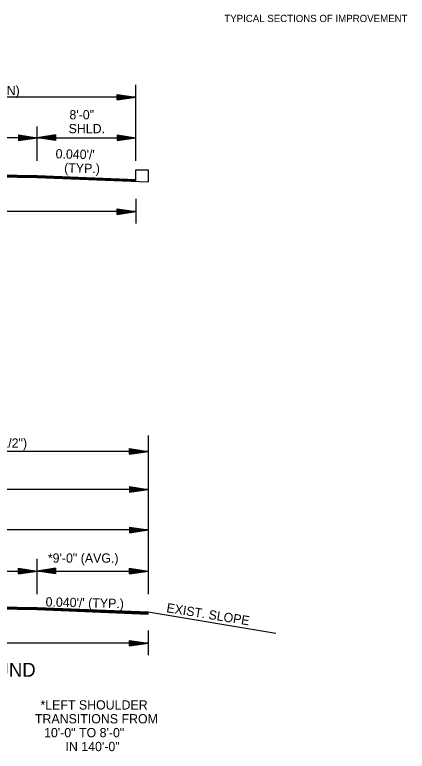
# Model space of a CAD drawing. Extents: x 542112 to 1930787, y -1968972 to 596640.
# Drawn here: x 545437 to 545755, y -1958354 to -1957756 of the extents above; entities that cross this region are included whole.
import ezdxf

# ---------------------------------------------------------------- set-up
doc = ezdxf.new("R2010")
doc.units = 0
for name, color, linetype in [('R_Border', 7, 'Continuous'), ('R_Border Prem', 7, 'Continuous'), ('R_Draft', 7, 'Continuous')]:
    doc.layers.add(name, color=color, linetype=linetype)

msp = doc.modelspace()

# ---------------------------------------------------------------- linework, layer by layer
at = {"layer": 'R_Border'}
for p, q in [((545534.98, -1957891.55), (545534.98, -1957882.14)), ((545534.98, -1957882.14), (545545.15, -1957882.14)), ((545545.15, -1957882.14), (545545.15, -1957891.96))]:
    msp.add_line(p, q, dxfattribs=at)
at = {"layer": 'R_Draft'}
for p, q in [((545534.98, -1957874.9), (545534.98, -1957813.41)), ((545534.98, -1957823.3), (545134.98, -1957823.3)), ((545504.98, -1957823.3), (545224.98, -1957823.3)), ((545519.98, -1957821.05), (545534.98, -1957823.3)), ((545519.98, -1957825.55), (545519.98, -1957821.05)), ((545519.98, -1957821.43), (545532.48, -1957823.3)), ((545519.98, -1957821.81), (545529.9, -1957823.3)), ((545519.98, -1957822.19), (545527.4, -1957823.3)), ((545519.98, -1957822.57), (545524.86, -1957823.3)), ((545519.98, -1957822.95), (545522.35, -1957823.3)), ((545519.98, -1957825.55), (545534.98, -1957823.3)), ((545519.98, -1957824.03), (545524.86, -1957823.3)), ((545519.98, -1957824.8), (545529.9, -1957823.3)), ((545519.98, -1957825.18), (545532.48, -1957823.3)), ((545519.98, -1957824.42), (545527.4, -1957823.3)), ((545519.98, -1957823.66), (545522.35, -1957823.3)), ((545454.98, -1957874.9), (545454.98, -1957846.95)), ((545454.98, -1957856.14), (545334.98, -1957856.14)), ((545439.98, -1957853.89), (545454.98, -1957856.14)), ((545439.98, -1957853.89), (545439.98, -1957858.39)), ((545439.98, -1957854.26), (545452.48, -1957856.14)), ((545439.98, -1957854.65), (545449.9, -1957856.14)), ((545439.98, -1957855.02), (545447.4, -1957856.14)), ((545439.98, -1957855.41), (545444.86, -1957856.14)), ((545439.98, -1957855.79), (545442.35, -1957856.14)), ((545439.98, -1957858.39), (545454.98, -1957856.14)), ((545439.98, -1957856.87), (545444.86, -1957856.14)), ((545439.98, -1957857.63), (545449.9, -1957856.14)), ((545439.98, -1957858.01), (545452.48, -1957856.14)), ((545439.98, -1957857.26), (545447.4, -1957856.14)), ((545439.98, -1957856.49), (545442.35, -1957856.14)), ((545469.98, -1957853.89), (545454.98, -1957856.14)), ((545454.98, -1957856.14), (545534.98, -1957856.14)), ((545469.98, -1957858.39), (545454.98, -1957856.14)), ((545469.98, -1957854.26), (545457.49, -1957856.14)), ((545469.98, -1957858.01), (545457.49, -1957856.14)), ((545469.98, -1957854.65), (545460.07, -1957856.14)), ((545469.98, -1957857.63), (545460.07, -1957856.14)), ((545469.98, -1957855.02), (545462.57, -1957856.14)), ((545469.98, -1957857.26), (545462.57, -1957856.14)), ((545469.98, -1957855.41), (545465.11, -1957856.14)), ((545469.98, -1957856.87), (545465.11, -1957856.14)), ((545469.98, -1957855.79), (545467.61, -1957856.14)), ((545469.98, -1957856.49), (545467.61, -1957856.14)), ((545469.98, -1957853.89), (545469.98, -1957858.39)), ((545519.98, -1957853.89), (545534.98, -1957856.14)), ((545519.98, -1957853.89), (545519.98, -1957858.39)), ((545519.98, -1957854.26), (545532.48, -1957856.14)), ((545519.98, -1957854.65), (545529.9, -1957856.14)), ((545519.98, -1957855.02), (545527.4, -1957856.14)), ((545519.98, -1957855.41), (545524.86, -1957856.14)), ((545519.98, -1957855.79), (545522.35, -1957856.14)), ((545519.98, -1957858.39), (545534.98, -1957856.14)), ((545519.98, -1957856.87), (545524.86, -1957856.14)), ((545519.98, -1957857.63), (545529.9, -1957856.14)), ((545519.98, -1957858.01), (545532.48, -1957856.14)), ((545519.98, -1957857.26), (545527.4, -1957856.14)), ((545519.98, -1957856.49), (545522.35, -1957856.14)), ((545334.98, -1957884.45), (545454.98, -1957886.85)), ((545334.98, -1957884.75), (545454.98, -1957887.15)), ((545334.98, -1957885.05), (545454.98, -1957887.45)), ((545334.98, -1957885.35), (545454.98, -1957887.75)), ((545334.98, -1957885.65), (545454.98, -1957888.05)), ((545334.98, -1957885.95), (545454.98, -1957888.35)), ((545334.98, -1957886.12), (545454.98, -1957888.52)), ((545454.98, -1957886.85), (545534.98, -1957890.05)), ((545454.98, -1957887.15), (545534.98, -1957890.35)), ((545454.98, -1957887.45), (545534.98, -1957890.65)), ((545454.98, -1957887.75), (545534.98, -1957890.95)), ((545454.98, -1957888.05), (545534.98, -1957891.25)), ((545454.98, -1957888.35), (545545.15, -1957891.96)), ((545534.98, -1957905.86), (545534.98, -1957925.86)), ((545534.98, -1957916.11), (545134.98, -1957916.11)), ((545519.98, -1957913.86), (545534.98, -1957916.11)), ((545519.98, -1957918.36), (545519.98, -1957913.86)), ((545519.98, -1957914.23), (545532.48, -1957916.11)), ((545519.98, -1957914.61), (545529.9, -1957916.11)), ((545519.98, -1957914.99), (545527.4, -1957916.11)), ((545519.98, -1957915.37), (545524.86, -1957916.11)), ((545519.98, -1957915.75), (545522.35, -1957916.11)), ((545519.98, -1957918.36), (545534.98, -1957916.11)), ((545519.98, -1957916.83), (545524.86, -1957916.11)), ((545519.98, -1957917.6), (545529.9, -1957916.11)), ((545519.98, -1957917.98), (545532.48, -1957916.11)), ((545519.98, -1957917.22), (545527.4, -1957916.11)), ((545519.98, -1957916.46), (545522.35, -1957916.11)), ((545544.99, -1958097.79), (545544.99, -1958226.47)), ((545544.99, -1958110.55), (545144.98, -1958110.55)), ((545529.99, -1958108.3), (545544.99, -1958110.55)), ((545529.99, -1958112.8), (545529.99, -1958108.3)), ((545529.99, -1958108.67), (545542.48, -1958110.55)), ((545529.99, -1958109.06), (545539.9, -1958110.55)), ((545529.99, -1958109.43), (545537.4, -1958110.55)), ((545529.99, -1958109.81), (545534.86, -1958110.55)), ((545529.99, -1958110.2), (545532.36, -1958110.55)), ((545529.99, -1958112.8), (545544.99, -1958110.55)), ((545529.99, -1958111.28), (545534.86, -1958110.55)), ((545529.99, -1958112.04), (545539.9, -1958110.55)), ((545529.99, -1958112.42), (545542.48, -1958110.55)), ((545529.99, -1958111.67), (545537.4, -1958110.55)), ((545529.99, -1958110.9), (545532.36, -1958110.55)), ((545544.99, -1958141.42), (545144.98, -1958141.42)), ((545529.99, -1958139.17), (545544.99, -1958141.42)), ((545529.99, -1958139.17), (545529.99, -1958143.67)), ((545529.99, -1958139.54), (545542.48, -1958141.42)), ((545529.99, -1958139.93), (545539.9, -1958141.42)), ((545529.99, -1958140.3), (545537.4, -1958141.42)), ((545529.99, -1958140.69), (545534.86, -1958141.42)), ((545529.99, -1958141.07), (545532.36, -1958141.42)), ((545529.99, -1958143.67), (545544.99, -1958141.42)), ((545529.99, -1958142.15), (545534.86, -1958141.42)), ((545529.99, -1958142.91), (545539.9, -1958141.42)), ((545529.99, -1958143.29), (545542.48, -1958141.42)), ((545529.99, -1958142.54), (545537.4, -1958141.42)), ((545529.99, -1958141.77), (545532.36, -1958141.42)), ((545529.99, -1958172.1), (545544.99, -1958174.35)), ((545529.99, -1958172.1), (545529.99, -1958176.6)), ((545529.99, -1958172.47), (545542.48, -1958174.35)), ((545529.99, -1958172.86), (545539.9, -1958174.35)), ((545544.99, -1958174.35), (545144.98, -1958174.35)), ((545529.99, -1958173.23), (545537.4, -1958174.35)), ((545529.99, -1958173.62), (545534.86, -1958174.35)), ((545529.99, -1958174), (545532.36, -1958174.35)), ((545529.99, -1958176.6), (545544.99, -1958174.35)), ((545529.99, -1958175.08), (545534.86, -1958174.35)), ((545529.99, -1958175.84), (545539.9, -1958174.35)), ((545529.99, -1958176.22), (545542.48, -1958174.35)), ((545529.99, -1958175.47), (545537.4, -1958174.35)), ((545529.99, -1958174.7), (545532.36, -1958174.35)), ((545454.98, -1958226.47), (545454.98, -1958197.75)), ((545334.98, -1958207.64), (545454.98, -1958207.64)), ((545439.98, -1958205.39), (545454.98, -1958207.64)), ((545439.98, -1958209.89), (545439.98, -1958205.39)), ((545439.98, -1958205.77), (545452.48, -1958207.64)), ((545439.98, -1958206.15), (545449.9, -1958207.64)), ((545439.98, -1958206.53), (545447.4, -1958207.64)), ((545439.98, -1958206.91), (545444.86, -1958207.64)), ((545439.98, -1958207.29), (545442.35, -1958207.64)), ((545439.98, -1958209.89), (545454.98, -1958207.64)), ((545439.98, -1958208.37), (545444.86, -1958207.64)), ((545439.98, -1958209.14), (545449.9, -1958207.64)), ((545439.98, -1958209.52), (545452.48, -1958207.64)), ((545439.98, -1958208.76), (545447.4, -1958207.64)), ((545439.98, -1958208), (545442.35, -1958207.64)), ((545469.98, -1958205.39), (545454.98, -1958207.64)), ((545454.98, -1958207.64), (545544.99, -1958207.64)), ((545469.98, -1958209.89), (545454.98, -1958207.64)), ((545469.98, -1958205.77), (545457.49, -1958207.64)), ((545469.98, -1958209.52), (545457.49, -1958207.64)), ((545469.98, -1958206.15), (545460.07, -1958207.64)), ((545469.98, -1958209.14), (545460.07, -1958207.64)), ((545469.98, -1958206.53), (545462.57, -1958207.64)), ((545469.98, -1958208.76), (545462.57, -1958207.64)), ((545469.98, -1958206.92), (545465.11, -1958207.64)), ((545469.98, -1958208.38), (545465.11, -1958207.64)), ((545469.98, -1958207.29), (545467.61, -1958207.64)), ((545469.98, -1958208), (545467.61, -1958207.64)), ((545469.98, -1958205.39), (545469.98, -1958209.89)), ((545529.99, -1958205.39), (545544.99, -1958207.64)), ((545529.99, -1958209.89), (545529.99, -1958205.39)), ((545529.99, -1958205.77), (545542.48, -1958207.64)), ((545529.99, -1958206.15), (545539.9, -1958207.64)), ((545529.99, -1958206.53), (545537.4, -1958207.64)), ((545529.99, -1958206.91), (545534.86, -1958207.64)), ((545529.99, -1958207.29), (545532.36, -1958207.64)), ((545529.99, -1958209.89), (545544.99, -1958207.64)), ((545529.99, -1958208.37), (545534.86, -1958207.64)), ((545529.99, -1958209.14), (545539.9, -1958207.64)), ((545529.99, -1958209.52), (545542.48, -1958207.64)), ((545529.99, -1958208.76), (545537.4, -1958207.64)), ((545529.99, -1958208), (545532.36, -1958207.64)), ((545334.98, -1958234.85), (545454.98, -1958237.25)), ((545334.98, -1958235.15), (545454.98, -1958237.55)), ((545334.98, -1958235.45), (545454.98, -1958237.85)), ((545334.98, -1958235.75), (545454.98, -1958238.15)), ((545334.98, -1958236.05), (545454.98, -1958238.45)), ((545334.98, -1958236.35), (545454.98, -1958238.75)), ((545334.98, -1958236.52), (545454.98, -1958238.92)), ((545454.98, -1958237.25), (545544.99, -1958240.85)), ((545454.98, -1958237.55), (545544.99, -1958241.15)), ((545454.98, -1958237.85), (545544.99, -1958241.45)), ((545454.98, -1958238.15), (545544.99, -1958241.75)), ((545454.98, -1958238.45), (545544.99, -1958242.05)), ((545454.98, -1958238.75), (545544.99, -1958242.35)), ((545454.98, -1958238.92), (545544.99, -1958242.52)), ((545544.99, -1958240.85), (545648.67, -1958258.13)), ((545544.99, -1958242.52), (545544.99, -1958240.85)), ((545544.99, -1958255.86), (545544.99, -1958275.86)), ((545544.99, -1958266.11), (545144.98, -1958266.11)), ((545529.99, -1958263.86), (545544.99, -1958266.11)), ((545529.99, -1958268.36), (545529.99, -1958263.86)), ((545529.99, -1958264.23), (545542.48, -1958266.11)), ((545529.99, -1958264.61), (545539.9, -1958266.11)), ((545529.99, -1958264.99), (545537.4, -1958266.11)), ((545529.99, -1958265.37), (545534.86, -1958266.11)), ((545529.99, -1958265.75), (545532.36, -1958266.11)), ((545529.99, -1958268.36), (545544.99, -1958266.11)), ((545529.99, -1958266.83), (545534.86, -1958266.11)), ((545529.99, -1958267.6), (545539.9, -1958266.11)), ((545529.99, -1958267.98), (545542.48, -1958266.11)), ((545529.99, -1958267.22), (545537.4, -1958266.11)), ((545529.99, -1958266.46), (545532.36, -1958266.11))]:
    msp.add_line(p, q, dxfattribs=at)

# ---------------------------------------------------------------- texts
at = {"layer": 'R_Border Prem'}
msp.add_text('TYPICAL SECTIONS OF IMPROVEMENT', height=5.862, rotation=360, dxfattribs=at).set_placement((545606.81, -1957762.37))
at = {"layer": 'R_Draft'}
for s, height, p in [('40\'-0" CLEAR ROADWAY (HYDRODEMOLITION)', 7.5, (545216.44, -1957821.63)), ('8\'-0"', 7.5, (545481.25, -1957841.28)), ('SHLD.', 7.5, (545480.57, -1957852.53)), ('40\'-0" (AVG.) ACHM SURFACE COURSE (1/2")', 7.5, (545232.21, -1958107.53)), ('*9\'-0" (AVG.)', 7.5, (545463.73, -1958200.85)), ('2 LANE ROADWAY - EAST BOUND', 11.25, (545208.93, -1958293.35)), ('*LEFT SHOULDER', 7.5, (545457.71, -1958319.96)), ('TRANSITIONS FROM', 7.5, (545453.25, -1958331.21)), ('10\'-0" TO 8\'-0"', 7.5, (545460.66, -1958342.46)), ('IN 140\'-0"', 7.5, (545478.03, -1958353.71))]:
    msp.add_text(s, height=height, dxfattribs=at).set_placement(p)
for s, rotation, p in [("0.040'/'", 358.68162, (545469.96, -1957872.9)), ('(TYP.)', 358.68162, (545476.9, -1957884.31)), ("0.040'/' (TYP.)", 358.68162, (545461.84, -1958236.35)), ('EXIST. SLOPE', 350.84656, (545559.52, -1958240.95))]:
    msp.add_text(s, height=7.5, rotation=rotation, dxfattribs=at).set_placement(p)

doc.saveas('drawing.dxf')
